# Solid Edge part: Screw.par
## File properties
Document Number: 16
Revision: A
File Size: 0
Number of Sheets: 0
Number of Objects: 0
Author: jmrobins
Template: NORMAL.PAR
Last saved by: rkriggs
Revision: 57
Application: Solid Edge
Quantité: 2
Density: 0.00000775 kg/mm^3
Accuracy: 0.99
Material: Stainless steel
Face Style: Steel
Fill Style: ANSI32(Steel)
Virtual Style: Stainless steel
Coef. of Thermal Exp: 1.6e-05
Thermal Conductivity: 17.0
Specific Heat: 502.0
Modulus of Elasticity: 193053196000.0
Poission's Ratio: 0.29
Yield Stress: 310264065.0
Ultimate Stress: 641212401.0
Elongation: 0.0
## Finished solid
Body 1: solid body, 20 faces, 36 edges, 18 vertices.
  Faces by surface: plane 16, cylinder 2, cone 1, torus 1
  Edges by curve: line 30, circle 6
Bounding box of the edges (mm; curved faces can reach further): 13.000 x 33.000 x 13.000, from (-6.5, -8, -6.5) to (6.5, 25, 6.5).
Cylindrical faces by radius (mm): R4 x1, R6.5 x1
Conical faces (half-angle, radius in mm at the cone's reference point): 45 deg R3.375 x1
Toroidal faces (ring radius, tube radius in mm): R6 r0.5 x1
Planar faces by outward normal: +y 2, +z 1, -y 2, -z 1, oblique 10
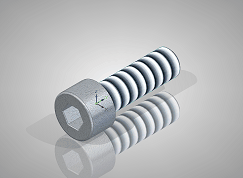
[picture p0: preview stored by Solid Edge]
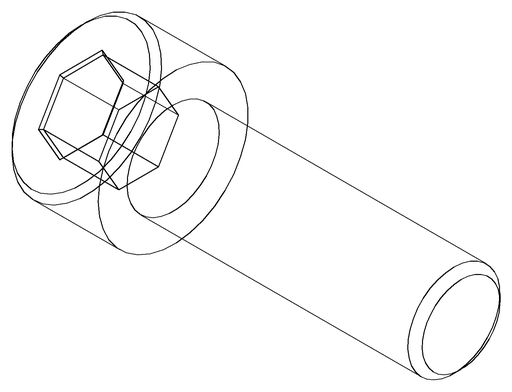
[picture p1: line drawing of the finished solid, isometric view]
